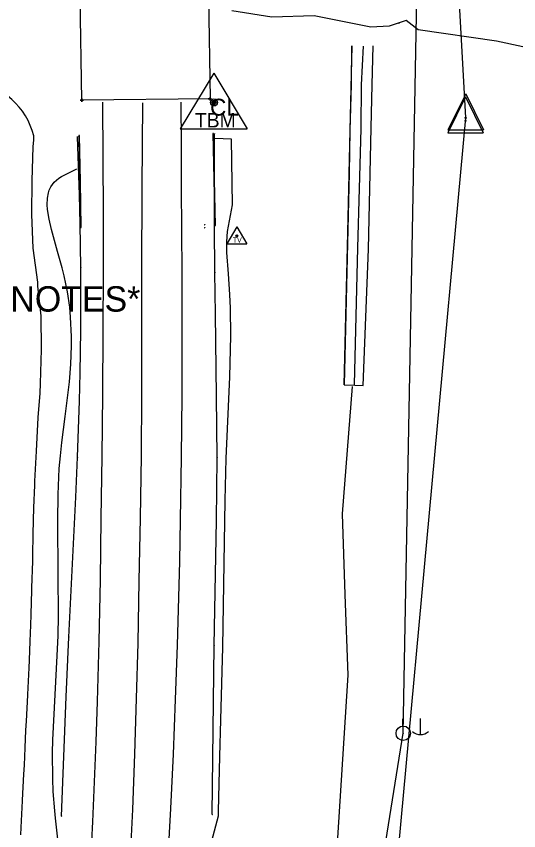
# Model space of a CAD drawing. Extents: x 1674300 to 1677920, y 225056 to 231852.
# Drawn here: x 1677422.6 to 1677571.2, y 228906.3 to 229147 of the extents above; entities that cross this region are included whole.
import ezdxf

# ---------------------------------------------------------------- set-up
doc = ezdxf.new("R2010")
doc.units = 0
for name, color, linetype in [('R_Proposed Const Limits_Fill', 7, 'Continuous'), ('S_BRIDGE', 7, 'Continuous'), ('S_BRIDGE_ANNOT', 7, 'Continuous'), ('S_CAL_CORNER_ANNOT', 7, 'Continuous'), ('S_CURB', 7, 'Continuous'), ('S_DITCHLINE', 7, 'Continuous'), ('S_EDGE_CONCRETE', 7, 'Continuous'), ('S_EDGE_PAVEMENT', 7, 'Continuous'), ('S_ELECTRIC_UTILITIES', 7, 'Continuous'), ('S_EXIST_ROW', 7, 'Continuous'), ('S_GUARDRAIL', 7, 'Continuous'), ('S_MSC_PT_SYM', 7, 'Continuous'), ('S_PAVEMENT_CROWN', 7, 'Continuous'), ('S_PRIMARY_CTL', 7, 'Continuous'), ('S_RDW_PT_SYM', 7, 'Continuous'), ('S_SECONDARY_CTL', 7, 'Continuous'), ('S_SHOULDER', 7, 'Continuous'), ('S_STR_PT_SYM', 7, 'Continuous'), ('S_STREAM', 7, 'Continuous'), ('S_UTILITY_POLE', 7, 'Continuous'), ('S_UTL_PT_SYM', 7, 'Continuous')]:
    doc.layers.add(name, color=color, linetype=linetype)

msp = doc.modelspace()

# ---------------------------------------------------------------- linework, layer by layer
at = {"layer": 'R_Proposed Const Limits_Fill'}
msp.add_lwpolyline([(1677423.87, 228905.08), (1677423.97, 228907.29), (1677424.41, 228915.15), (1677424.41, 228915.4), (1677424.8, 228923.01), (1677424.97, 228925.73), (1677425.17, 228930.88), (1677425.42, 228936.06), (1677425.56, 228938.74), (1677425.96, 228946.38), (1677425.97, 228946.61), (1677426.33, 228954.48), (1677426.44, 228956.72), (1677426.65, 228962.35), (1677426.83, 228967.05), (1677426.95, 228970.23), (1677427.17, 228977.4), (1677427.18, 228978.1), (1677427.43, 228985.98), (1677427.46, 228987.74), (1677427.55, 228993.86), (1677427.66, 228998.09), (1677427.78, 229001.74), (1677428.03, 229008.45), (1677428.08, 229009.63), (1677428.52, 229018.49), (1677429.06, 229028.5), (1677429.66, 229035.68), (1677429.75, 229038.51), (1677430.01, 229048.52), (1677429.88, 229058.52), (1677428.95, 229067.25), (1677428.96, 229068.5), (1677427.59, 229078.49), (1677427.11, 229088.48), (1677427.22, 229098.48), (1677427.56, 229108.49), (1677427.73, 229110.49), (1677427.72, 229111.69)], dxfattribs=at)
msp.add_arc((1677407.01, 229106.59), 21.33, 13.8139, 82.6226, dxfattribs=at)
at = {"layer": 'S_BRIDGE'}
for p, q in [((1677441.95, 229122.22), (1677441.12, 229176.97)), ((1677478.98, 229177.38), (1677479.86, 229122.68)), ((1677479.86, 229122.68), (1677441.95, 229122.22))]:
    msp.add_line(p, q, dxfattribs=at)
at = {"layer": 'S_CURB'}
msp.add_lwpolyline([(1677441.03, 229111.79), (1677441.26, 229098.22), (1677441.49, 229084.65), (1677441.72, 229084.58), (1677441.51, 229098.19), (1677441.3, 229111.8)], close=True, dxfattribs=at)
at = {"layer": 'S_DITCHLINE'}
for points in [[(1677522.63, 229038.26), (1677523.12, 229058.43), (1677523.6, 229078.59), (1677524.1, 229096.18), (1677524.6, 229113.77), (1677524.67, 229126.78), (1677525.27, 229138.2)], [(1677492.32, 228714.69), (1677496.91, 228738.44), (1677499.97, 228757.22), (1677503.03, 228775.99), (1677505.25, 228788.38), (1677507.46, 228800.77), (1677510.6, 228824.19), (1677513.73, 228847.61), (1677514.83, 228851.31), (1677515.02, 228854.93), (1677514.96, 228858.41), (1677514.63, 228862.29), (1677513.48, 228868.18), (1677515.51, 228885.41), (1677517.54, 228902.65), (1677519.12, 228927.5), (1677520.71, 228952.35), (1677519.88, 228976.18), (1677519.06, 229000), (1677520.55, 229018.83), (1677522.04, 229037.67)]]:
    msp.add_lwpolyline(points, dxfattribs=at)
at = {"layer": 'S_EDGE_CONCRETE'}
for points in [[(1677519.57, 229038.13), (1677520.04, 229058.54), (1677520.52, 229078.95), (1677520.93, 229096.11), (1677521.34, 229113.27), (1677521.67, 229126.86), (1677521.82, 229138.35), (1677521.53, 229125.82), (1677521.25, 229113.29), (1677520.97, 229100.76), (1677520.69, 229088.24), (1677520.41, 229075.71), (1677520.13, 229063.18), (1677519.85, 229050.65)], [(1677480.74, 229112.39), (1677481.01, 229098.81), (1677481.28, 229085.22), (1677481.44, 229085.19), (1677481.19, 229098.78), (1677480.94, 229112.36)]]:
    msp.add_lwpolyline(points, close=True, dxfattribs=at)
msp.add_lwpolyline([(1677519.58, 229038.11), (1677522.68, 229037.98), (1677525.2, 229037.96), (1677525.95, 229058.08), (1677526.69, 229078.2), (1677527.11, 229096.11), (1677527.53, 229114.03), (1677527.87, 229126.76), (1677528.09, 229138.32)], dxfattribs=at)
at = {"layer": 'S_EDGE_PAVEMENT'}
for points in [[(1677444.36, 228891.83), (1677445.2, 228908.97), (1677446.16, 228932.65), (1677446.57, 228944.49), (1677447.07, 228962.26), (1677447.45, 228980.47), (1677447.69, 228998.68), (1677447.94, 229016.89), (1677448.12, 229035.35), (1677448.29, 229053.8), (1677448.38, 229072.25), (1677448.38, 229088.73), (1677448.28, 229105.21), (1677448.18, 229121.69)], [(1677467.02, 228889.58), (1677468.3, 228912.92), (1677469.04, 228929.01), (1677469.62, 228945.1), (1677470.21, 228961.2), (1677470.9, 228985.89), (1677471.17, 228998.24), (1677471.46, 229016.76), (1677471.6, 229034.93), (1677471.6, 229053.1), (1677471.6, 229071.27), (1677471.53, 229083.86), (1677471.46, 229096.45), (1677471.39, 229109.03), (1677471.32, 229121.62)]]:
    msp.add_lwpolyline(points, dxfattribs=at)
at = {"layer": 'S_ELECTRIC_UTILITIES'}
for p, q in [((1677537.01, 228935.14), (1677541.67, 229188.26)), ((1677492.08, 228657.14), (1677537.01, 228935.14))]:
    msp.add_line(p, q, dxfattribs=at)
at = {"layer": 'S_EXIST_ROW'}
for p, q in [((1677555.5, 229117.02), (1677521.25, 229735.57)), ((1677555.45, 229123.25), (1677550.16, 229112.61)), ((1677555.52, 229124.11), (1677550.23, 229113.47)), ((1677555.45, 229123.25), (1677560.68, 229112.61)), ((1677555.52, 229124.11), (1677560.76, 229113.47)), ((1677527.92, 228816.46), (1677555.5, 229117.02)), ((1677555.43, 229116.15), (1677555.43, 229116.15)), ((1677555.5, 229117.02), (1677555.5, 229117.02)), ((1677550.23, 229113.47), (1677560.76, 229113.47)), ((1677550.16, 229112.61), (1677560.68, 229112.61))]:
    msp.add_line(p, q, dxfattribs=at)
for centre, radius in [((1677555.43, 229116.15), 0.18), ((1677555.5, 229117.02), 0.18), ((1677555.43, 229116.15), 0.09), ((1677555.5, 229117.02), 0.09)]:
    msp.add_circle(centre, radius, dxfattribs=at)
at = {"layer": 'S_GUARDRAIL'}
for p, q in [((1677441.28, 229094.28), (1677440.67, 229111.44)), ((1677481.21, 229085), (1677481.23, 229112.34)), ((1677441.49, 229085.7), (1677441.28, 229094.28)), ((1677441.66, 229072.83), (1677441.49, 229085.7)), ((1677481.3, 229071.32), (1677481.21, 229085)), ((1677441.63, 229054.13), (1677441.66, 229072.83)), ((1677481.45, 229059.15), (1677481.3, 229071.32)), ((1677481.81, 229034.81), (1677481.45, 229059.15)), ((1677441.44, 229041.66), (1677441.63, 229054.13)), ((1677441.24, 229033.35), (1677441.44, 229041.66)), ((1677481.93, 229016.55), (1677481.81, 229034.81)), ((1677440.69, 229016.73), (1677441.24, 229033.35)), ((1677440.18, 229004.92), (1677440.69, 229016.73)), ((1677481.78, 228998.05), (1677481.93, 229016.55)), ((1677439.02, 228981.3), (1677440.18, 229004.92)), ((1677481.09, 228961.05), (1677481.78, 228998.05)), ((1677438.13, 228963.59), (1677439.02, 228981.3)), ((1677437.33, 228945.95), (1677438.13, 228963.59)), ((1677480.86, 228944.41), (1677481.09, 228961.05)), ((1677435.91, 228910.66), (1677437.33, 228945.95)), ((1677480.54, 228911.14), (1677480.86, 228944.41))]:
    msp.add_line(p, q, dxfattribs=at)
at = {"layer": 'S_MSC_PT_SYM'}
for points in [[(1677535.79, 229145.03), (1677535.79, 229145.08), (1677535.79, 229145.03), (1677535.74, 229145.03), (1677535.79, 229145.03), (1677535.79, 229144.98), (1677535.79, 229145.03), (1677535.84, 229145.03)], [(1677478.28, 229084.57), (1677478.28, 229084.62), (1677478.28, 229084.57), (1677478.23, 229084.57), (1677478.28, 229084.57), (1677478.28, 229084.52), (1677478.28, 229084.57), (1677478.33, 229084.57)], [(1677478.29, 229085.42), (1677478.29, 229085.47), (1677478.29, 229085.42), (1677478.24, 229085.42), (1677478.29, 229085.42), (1677478.29, 229085.37), (1677478.29, 229085.42), (1677478.34, 229085.42)]]:
    msp.add_lwpolyline(points, dxfattribs=at)
at = {"layer": 'S_PAVEMENT_CROWN'}
msp.add_lwpolyline([(1677455.99, 228890.92), (1677457.05, 228912.61), (1677457.66, 228928.98), (1677458.11, 228945.37), (1677458.57, 228961.75), (1677458.95, 228980.23), (1677459.33, 228998.7), (1677459.56, 229017.18), (1677459.66, 229035.28), (1677459.68, 229053.38), (1677459.71, 229071.47), (1677459.84, 229096.45), (1677459.96, 229121.43)], dxfattribs=at)
at = {"layer": 'S_PRIMARY_CTL'}
for p, q in [((1677481.03, 229130.28), (1677470.99, 229113.77)), ((1677481.03, 229130.28), (1677490.85, 229113.77)), ((1677470.99, 229113.77), (1677490.85, 229113.77))]:
    msp.add_line(p, q, dxfattribs=at)
for radius in [1.04, 0.609, 0.344]:
    msp.add_circle((1677481.03, 229121.58), radius, dxfattribs=at)
at = {"layer": 'S_RDW_PT_SYM'}
for points in [[(1677440.67, 229111.44), (1677440.67, 229111.49), (1677440.67, 229111.44), (1677440.62, 229111.44), (1677440.67, 229111.44), (1677440.67, 229111.39), (1677440.67, 229111.44), (1677440.72, 229111.44)], [(1677481.23, 229112.34), (1677481.23, 229112.39), (1677481.23, 229112.34), (1677481.18, 229112.34), (1677481.23, 229112.34), (1677481.23, 229112.29), (1677481.23, 229112.34), (1677481.28, 229112.34)], [(1677441.66, 229072.83), (1677441.66, 229072.88), (1677441.66, 229072.83), (1677441.61, 229072.83), (1677441.66, 229072.83), (1677441.66, 229072.78), (1677441.66, 229072.83), (1677441.71, 229072.83)], [(1677481.3, 229071.32), (1677481.3, 229071.37), (1677481.3, 229071.32), (1677481.25, 229071.32), (1677481.3, 229071.32), (1677481.3, 229071.27), (1677481.3, 229071.32), (1677481.35, 229071.32)], [(1677440.69, 229016.73), (1677440.69, 229016.78), (1677440.69, 229016.73), (1677440.64, 229016.73), (1677440.69, 229016.73), (1677440.69, 229016.68), (1677440.69, 229016.73), (1677440.74, 229016.73)], [(1677481.93, 229016.55), (1677481.93, 229016.6), (1677481.93, 229016.55), (1677481.88, 229016.55), (1677481.93, 229016.55), (1677481.93, 229016.5), (1677481.93, 229016.55), (1677481.98, 229016.55)], [(1677438.13, 228963.59), (1677438.13, 228963.64), (1677438.13, 228963.59), (1677438.08, 228963.59), (1677438.13, 228963.59), (1677438.13, 228963.54), (1677438.13, 228963.59), (1677438.18, 228963.59)], [(1677481.09, 228961.05), (1677481.09, 228961.1), (1677481.09, 228961.05), (1677481.04, 228961.05), (1677481.09, 228961.05), (1677481.09, 228961), (1677481.09, 228961.05), (1677481.14, 228961.05)], [(1677435.91, 228910.66), (1677435.91, 228910.71), (1677435.91, 228910.66), (1677435.86, 228910.66), (1677435.91, 228910.66), (1677435.91, 228910.61), (1677435.91, 228910.66), (1677435.96, 228910.66)], [(1677480.54, 228911.14), (1677480.54, 228911.19), (1677480.54, 228911.14), (1677480.49, 228911.14), (1677480.54, 228911.14), (1677480.54, 228911.09), (1677480.54, 228911.14), (1677480.59, 228911.14)]]:
    msp.add_lwpolyline(points, dxfattribs=at)
at = {"layer": 'S_SECONDARY_CTL'}
for p, q in [((1677487.81, 229084.79), (1677484.8, 229079.84)), ((1677487.81, 229084.79), (1677490.75, 229079.84)), ((1677484.8, 229079.84), (1677490.75, 229079.84))]:
    msp.add_line(p, q, dxfattribs=at)
for radius in [0.311, 0.183, 0.103]:
    msp.add_circle((1677487.81, 229082.18), radius, dxfattribs=at)
at = {"layer": 'S_SHOULDER'}
for points in [[(1677476.72, 228889.65), (1677482.34, 228910.72), (1677482.37, 228912.13), (1677482.74, 228928.29), (1677483.05, 228939.06), (1677483.61, 228960.61), (1677483.9, 228979.19), (1677484.3, 229003.95), (1677484.68, 229016.32), (1677485.72, 229040.51), (1677485.97, 229052.63), (1677485.87, 229060.73), (1677485.72, 229064.79), (1677485.33, 229070.89), (1677484.86, 229077.21), (1677484.81, 229080.34), (1677485.03, 229083.45), (1677485.28, 229085), (1677486.51, 229091.31), (1677486.23, 229110.7), (1677481.28, 229110.91)], [(1677435.59, 228896.81), (1677434.14, 228910.02), (1677433.92, 228912.18), (1677433.47, 228917.9), (1677433.32, 228921.72), (1677433.29, 228929.34), (1677433.38, 228933.16), (1677433.72, 228940.81), (1677434.59, 228956.19), (1677434.91, 228963.94), (1677435.01, 228969.95), (1677434.96, 228981.99), (1677434.83, 228997.92), (1677434.94, 229005.74), (1677435.29, 229013.42), (1677435.59, 229017.18), (1677435.99, 229021.07), (1677436.97, 229028.74), (1677438.26, 229039.01), (1677438.71, 229044.26), (1677438.93, 229049.66), (1677438.92, 229052.43), (1677438.64, 229058.12), (1677438.35, 229061.06), (1677437.68, 229065.6), (1677436.71, 229070.31), (1677436.11, 229072.74), (1677434.73, 229077.57), (1677432.93, 229083.99), (1677432.24, 229087.06), (1677431.82, 229089.97), (1677431.74, 229091.35), (1677431.8, 229093.29), (1677432.09, 229094.89), (1677432.32, 229095.63), (1677432.78, 229096.67), (1677433.76, 229098.06), (1677435.12, 229099.22), (1677435.96, 229099.7), (1677440.46, 229101.97)]]:
    msp.add_lwpolyline(points, dxfattribs=at)
at = {"layer": 'S_STR_PT_SYM'}
for points in [[(1677479.86, 229122.68), (1677479.86, 229123.18), (1677479.86, 229122.68), (1677479.36, 229122.68), (1677479.86, 229122.68), (1677479.86, 229122.18), (1677479.86, 229122.68), (1677480.36, 229122.68)], [(1677441.95, 229122.22), (1677441.95, 229122.72), (1677441.95, 229122.22), (1677441.45, 229122.22), (1677441.95, 229122.22), (1677441.95, 229121.72), (1677441.95, 229122.22), (1677442.45, 229122.22)]]:
    msp.add_lwpolyline(points, dxfattribs=at)
at = {"layer": 'S_STREAM'}
msp.add_lwpolyline([(1677572.37, 229138.06), (1677564.56, 229139.66), (1677541.46, 229143.03), (1677537.87, 229145.79), (1677532.82, 229144.1), (1677527.43, 229143.82), (1677510.66, 229147.15), (1677498.12, 229146.82), (1677486.33, 229148.7)], dxfattribs=at)
at = {"layer": 'S_UTILITY_POLE'}
for p, q in [((1677536.88, 228937.28), (1677536.88, 228939.39)), ((1677542.05, 228939.47), (1677542.05, 228934.74))]:
    msp.add_line(p, q, dxfattribs=at)
msp.add_circle((1677537.01, 228935.14), 2.13, dxfattribs=at)
msp.add_arc((1677542.11, 228938.17), 3.41, 226.3972, 313.6028, dxfattribs=at)
at = {"layer": 'S_UTL_PT_SYM'}
msp.add_lwpolyline([(1677537.01, 228935.14), (1677537.01, 228935.19), (1677537.01, 228935.14), (1677536.96, 228935.14), (1677537.01, 228935.14), (1677537.01, 228935.09), (1677537.01, 228935.14), (1677537.06, 228935.14)], dxfattribs=at)

# ---------------------------------------------------------------- texts
at = {"layer": 'S_BRIDGE_ANNOT'}
msp.add_text('CL', height=5, dxfattribs=at).set_placement((1677479.86, 229117.68))
at = {"layer": 'S_CAL_CORNER_ANNOT'}
msp.add_text('*SEE CORNER NOTES*', height=7.5, dxfattribs=at).set_placement((1677347.8, 229059.76))
at = {"layer": 'S_PRIMARY_CTL'}
msp.add_text('TBM', height=4.287, rotation=360, dxfattribs=at).set_placement((1677475.37, 229114.19))
at = {"layer": 'S_SECONDARY_CTL'}
msp.add_text('TV', height=1.5, rotation=360, dxfattribs=at).set_placement((1677486.6, 229080.17))

doc.saveas('drawing.dxf')
